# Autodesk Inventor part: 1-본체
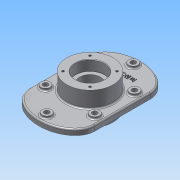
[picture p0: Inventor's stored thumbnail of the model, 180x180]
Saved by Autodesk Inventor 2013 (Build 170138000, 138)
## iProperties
Created: 2015-02
Part Number: 1-본체
Material: 알루미늄 6061
Document SubType Name: Modeling
Designer: Administrator
Mass: 1476.45 g
Surface Area: 942.609 cm^2
Volume: 613.321 cm^3
Density: 2.40731 g/cm^3
Author: Administrator
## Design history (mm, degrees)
sketch "스케치1"
  geometry: L1 (70, 60)-(-70, 60); L2 (-70, 60)-(-70, -60); L3 (-70, -60)-(70, -60); L4 (70, -60)-(70, 60); L5 (70, 60)-(-70, -60); L6 (-70, 60)-(70, -60); 7 further points; 2 other entities
  constraints: 12 end point, 6 midpoint, 3 horizontal, 2 parallel, 2 vertical alignment, 1 perpendicular, 8 other
  dimensions: "d0" = 140 distance of L1.start L1.end; "d2" = 120 distance of L3.end L1.start; "d3" = 50 distance from line of L1 point (0, 110); "d4" = 50 distance from line of point (0, -110) L3
extrude "돌출1" new body sketch "스케치1" distance "d5" = 12; taper "d6" = 0 deg
sketch "스케치3"
  geometry: L1 (70, -60)-(70, 60) reference; L2 (-70, 60)-(-70, -60) reference; L3 (53, 60)-(53, -60); L4 (-53, -60)-(-53, 60); C1 r 10 at (53, 42.733); C2 r 10 at (53, -42.733); C3 r 10 at (0, 93); C4 r 10 at (0, -93); C5 r 10 at (-53, 42.733); C6 r 10 at (-53, -42.733); 3 further points; 2 other entities
  constraints: 6 centre point, 5 equal radius, 4 end point, 4 point on line, 3 parallel, 2 vertical alignment, 10 other
  dimensions: "d32" = 17 distance between parallel lines of L1 L3; "d33" = 20 diameter of C1; "d34" = 85.46667 distance of C2.centre C1.centre; "d35" = 42.73333 vertical distance of C2.centre point (0, 0); "d74" = 85.46667 distance of C6.centre C5.centre; "d75" = 42.73333 vertical distance of C6.centre point (0, 0)
extrude "돌출3" join sketch "스케치3" distance "d36" = 5; taper "d37" = 0 deg
hole "구멍3" diameter "d40" = 11; stored, may be unused: countersink angle "d44" = 90 deg, drill point angle "d46" = 0 deg; dims "d38" = 10, "d39" = 10, "d41" = 6, "d42" = 4, "d43" = 2, "d45" = 8
hole "구멍4" diameter "d49" = 11; stored, may be unused: countersink angle "d53" = 90 deg, drill point angle "d55" = 0 deg; dims "d47" = 10, "d48" = 10, "d50" = 6, "d51" = 4, "d52" = 2, "d54" = 8
hole "구멍5" diameter "d58" = 11; stored, may be unused: countersink angle "d62" = 90 deg, drill point angle "d64" = 0 deg; dims "d56" = 10, "d57" = 10, "d59" = 6, "d60" = 4, "d61" = 2, "d63" = 8
hole "구멍6" diameter "d67" = 11; stored, may be unused: countersink angle "d71" = 90 deg, drill point angle "d73" = 0 deg; dims "d65" = 10, "d66" = 10, "d68" = 6, "d69" = 4, "d70" = 2, "d72" = 8
extrude "돌출4" join sketch "스케치3" distance "d76" = 5; taper "d77" = 0 deg
hole "구멍7" diameter "d80" = 11; stored, may be unused: countersink angle "d84" = 90 deg, drill point angle "d86" = 0 deg; dims "d78" = 10, "d79" = 10, "d81" = 6, "d82" = 4, "d83" = 2, "d85" = 8
hole "구멍8" diameter "d89" = 11; stored, may be unused: countersink angle "d93" = 90 deg, drill point angle "d95" = 0 deg; dims "d87" = 10, "d88" = 10, "d90" = 6, "d91" = 4, "d92" = 2, "d94" = 8
node "작업 평면1"
sketch "스케치4"
  geometry: C1 r 50 at (0, 0); 1 further point
  constraints: 1 centre point, 1 coincident
  dimensions: "d97" = 100 diameter of C1
extrude "돌출5" join sketch "스케치4" distance "d99" = 70; taper "d100" = 0 deg
hole "구멍9" diameter "d103" = 45; stored, may be unused: countersink angle "d107" = 90 deg, drill point angle "d109" = 0 deg; dims "d101" = 10, "d102" = 10, "d104" = 6, "d105" = 62, "d106" = 22, "d108" = 8
hole "구멍10" diameter "d112" = 45; stored, may be unused: countersink angle "d116" = 90 deg, drill point angle "d118" = 0 deg; dims "d110" = 10, "d111" = 10, "d113" = 6, "d114" = 62, "d115" = 22, "d117" = 8
sketch "스케치5"
  geometry: C1 r 50 at (0, 0) reference; C2 r 10 at (0, 93) reference; 1 further point
  constraints: 1 vertical alignment, 1 other
  dimensions: "d119" = 65 distance of C1.centre point (0, 65)
feature "엠보싱1" sketch "스케치5" dims "d0" = 140, "d2" = 120, "d3" = 50, "d4" = 50, "d120" = 1, "d121" = 0
sketch "스케치6"
  geometry: C1 r 31 at (0, 0) reference; C2 r 50 at (0, 0) reference; A1 r 41 centre (0, 0) between (-28.991, 28.991) and (28.991, 28.991); 2 further points
  constraints: 4 point on circle, 2 horizontal alignment, 2 vertical alignment, 1 centre point, 1 coincident
  dimensions: "d122" = 82 diameter of A1; "d124" = 90 deg dimension on C1.centre A1.end A1.start
hole "구멍11" sketch "스케치6" at (-28.991, 28.991), (28.991, 28.991), (28.991, -28.991), (-28.991, -28.991) diameter "d126" = 4.917; stored, may be unused: countersink angle "d130" = 90 deg, drill point angle "d132" = 118 deg; dims "d127" = 10, "d128" = 62, "d129" = 22, "d131" = 13
node "작업 평면2"
fillet "모깎기1" dims "d133" = 3
fillet "모깎기2" dims "d134" = 0.3
chamfer "모따기1" distance "d135" = 1; stored, may be unused: second distance "d136" = 2, angle "d137" = 45 deg
node "솔리드1"
mirror "대칭1"
other parameters: "d96" = 23
